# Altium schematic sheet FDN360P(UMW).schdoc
size 127 x 101 mm
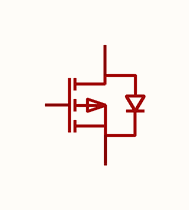
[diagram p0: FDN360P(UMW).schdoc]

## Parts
Q?  fdn360p(umw)  [SOT-23-3_L2.9-W1.3-P1.90-LS2.4-BR]  (value not drawn)

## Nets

Not connected (* = marked no-connect by the designer): Q? 1(G) 2(S) 3(D)

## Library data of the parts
Q? = fdn360p(umw): 数量:1个P沟道;漏源电压(Vdss):30V;连续漏极电流(Id):2A;导通电阻(RDS(on)):63mΩ@10V;耗散功率(Pd):500mW;阈值电压(Vgs(th)):1.9V;; Manufacturer: UMW(友台半导体); AddInBom: yes; ModelId: c62791f0466c4ae2a892c056b845b0ca; ModelName: SOT-23-3P_L2.9-W1.3-H1.0-LS2.4-P0.95; ModelTransform: 98.425,114.173,0,180,0,0,0.0005,-0.0005,0; Number: 1个P沟道; Drain to Source Voltage: 30V; Current - Continuous Drain(Id): 2A; Pd - Power Dissipation: 500mW; Gate Threshold Voltage (Vgs(th)): 1.9V; Gate Charge(Qg): 6.2nC; Input Capacitance(Ciss): 298pF; Reverse Transfer Capacitance (Crss@Vds): 39pF; Type: P沟道; Output Capacitance(Coss): 83pF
